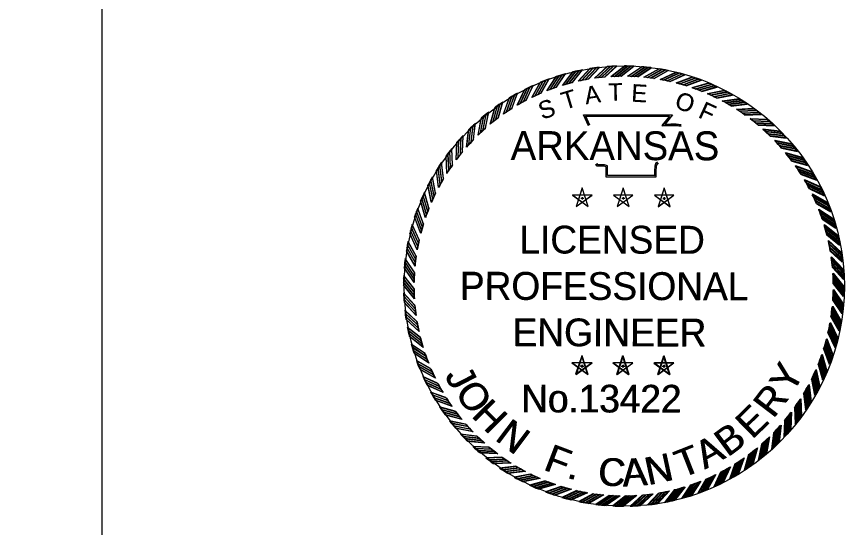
# Model space of a CAD drawing. Extents: x 0 to 38, y -1.3 to 22.5.
# Drawn here: x 33.533 to 38.047, y 15.315 to 18.1 of the extents above; entities that cross this region are included whole.
import ezdxf

# ---------------------------------------------------------------- set-up
doc = ezdxf.new("R2010")
doc.units = 0
for name, color, linetype in [('Default', 7, 'Continuous'), ('G-ANNO-STMP', 7, 'Continuous'), ('G-Border-Paper', 7, 'Continuous'), ('G-No Plot-Stamp-1', 7, 'Continuous'), ('G-No Plot-Stamp-2', 7, 'Continuous')]:
    doc.layers.add(name, color=color, linetype=linetype)

# ---------------------------------------------------------------- blocks, each defined once
blk = doc.blocks.new('STAR')
at = {"layer": 'Default'}
for p, q in [((-0.0001, 0.0615), (-0.0366, -0.0504)), ((0.0362, -0.0503), (0, 0.0617)), ((0.0587, 0.0188), (-0.059, 0.0189)), ((-0.0589, 0.0188), (0.0363, -0.0505)), ((-0.0365, -0.0503), (0.0589, 0.0188)), ((-0.0085, 0), (0.009, 0)), ((0, 0.0063), (0, -0.0085))]:
    blk.add_line(p, q, dxfattribs=at)
blk = doc.blocks.new('RP')
at = {"layer": 'Default'}
for p, q in [((-0.0781, 1.2656), (0.003, 1.33)), ((-0.058, 1.2667), (0.0216, 1.3299)), ((-0.0375, 1.2674), (0.0405, 1.3294)), ((-0.0176, 1.2679), (0.059, 1.3287))]:
    blk.add_line(p, q, dxfattribs=at)
for radius, start, end in [(1.33, 87.4562, 89.8699), (1.268, 90.7933, 93.5307)]:
    blk.add_arc((0, 0), radius, start, end, dxfattribs=at)

msp = doc.modelspace()

# ---------------------------------------------------------------- linework, layer by layer
at = {"layer": 'G-ANNO-STMP'}
for points in [[(36.6512, 17.5042), (36.6231, 17.5649), (37.1083, 17.5652), (37.0678, 17.5142), (37.1007, 17.5147), (37.1283, 17.515), (37.1558, 17.512)], [(36.6521, 17.5045), (36.6243, 17.5653), (37.1095, 17.5639), (37.0688, 17.5131), (37.1017, 17.5135), (37.1293, 17.5137), (37.1568, 17.5106)], [(36.6581, 17.5074), (36.6351, 17.5572), (37.0924, 17.5575), (37.0517, 17.5063), (37.1008, 17.507), (37.1279, 17.5073), (37.1549, 17.5044)], [(36.6591, 17.5077), (36.6363, 17.5576), (37.0935, 17.5563), (37.0526, 17.5053), (37.1018, 17.5058), (37.1289, 17.506), (37.1559, 17.503)], [(37.0319, 17.3008), (37.0236, 17.2941), (37.0208, 17.284), (37.0181, 17.2589), (37.0181, 17.2253), (36.7472, 17.2253), (36.7472, 17.2706), (36.7472, 17.2807), (36.7363, 17.284), (36.6977, 17.284), (36.6909, 17.2945)], [(37.0321, 17.2999), (37.0238, 17.2931), (37.021, 17.2831), (37.0182, 17.258), (37.0181, 17.2244), (36.7472, 17.2253), (36.7474, 17.2706), (36.7474, 17.2807), (36.7365, 17.2841), (36.6979, 17.2842), (36.6911, 17.2947)], [(37.027, 17.3068), (37.0168, 17.2985), (37.0133, 17.2855), (37.0104, 17.2593), (37.0104, 17.233), (36.7549, 17.233), (36.7549, 17.2706), (36.7549, 17.2864), (36.7374, 17.2917), (36.7019, 17.2917), (36.6973, 17.2987)], [(37.0273, 17.3058), (37.0171, 17.2976), (37.0135, 17.2846), (37.0105, 17.2584), (37.0104, 17.2321), (36.7549, 17.233), (36.7551, 17.2706), (36.7551, 17.2863), (36.7376, 17.2918), (36.7021, 17.2919), (36.6976, 17.2989)]]:
    msp.add_lwpolyline(points, dxfattribs=at)
at = {"layer": 'G-Border-Paper'}
msp.add_lwpolyline([(34, 22), (0, 22), (0, 0), (34, 0)], close=True, dxfattribs=at)
at = {"layer": 'G-No Plot-Stamp-1'}
msp.add_circle((36.8467, 16.6309), 1.2, dxfattribs=at)
at = {"layer": 'G-No Plot-Stamp-2'}
msp.add_circle((36.8467, 16.6309), 1.2, dxfattribs=at)

# ---------------------------------------------------------------- block references
at = {"layer": 'G-ANNO-STMP'}
for name, p, xscale, yscale, rotation in [('RP', (36.8439, 16.6311), 0.9020715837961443, 0.9020715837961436, 4.500000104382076), ('RP', (36.8418, 16.6308), 0.902071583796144, 0.9020715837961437, 4.304199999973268), ('RP', (36.8439, 16.6311), 0.902071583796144, 0.9020715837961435, 1.0438208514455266e-07), ('RP', (36.8418, 16.6308), 0.902071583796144, 0.9020715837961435, -0.19580000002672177), ('RP', (36.8439, 16.6311), 0.902071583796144, 0.9020715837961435, -4.499999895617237), ('RP', (36.8418, 16.6308), 0.9020715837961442, 0.9020715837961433, -4.695800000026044), ('RP', (36.8439, 16.6311), 0.9020715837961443, 0.9020715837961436, 18.000000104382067), ('RP', (36.8418, 16.6308), 0.9020715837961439, 0.9020715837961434, 17.804199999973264), ('RP', (36.8439, 16.6311), 0.9020715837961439, 0.9020715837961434, 13.500000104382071), ('RP', (36.8418, 16.6308), 0.902071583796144, 0.9020715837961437, 13.304199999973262), ('RP', (36.8439, 16.6311), 0.9020715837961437, 0.9020715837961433, 9.000000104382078), ('RP', (36.8418, 16.6308), 0.9020715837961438, 0.9020715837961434, 8.804199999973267), ('RP', (36.8439, 16.6311), 0.9020715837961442, 0.9020715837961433, -8.999999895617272), ('RP', (36.8418, 16.6308), 0.9020715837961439, 0.9020715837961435, -9.195800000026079), ('RP', (36.8439, 16.6311), 0.9020715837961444, 0.9020715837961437, -13.499999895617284), ('RP', (36.8418, 16.6308), 0.9020715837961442, 0.9020715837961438, -13.695800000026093), ('RP', (36.8439, 16.6311), 0.9020715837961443, 0.9020715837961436, -17.99999989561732), ('RP', (36.8418, 16.6308), 0.9020715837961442, 0.9020715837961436, -18.19580000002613), ('RP', (36.8439, 16.6311), 0.9020715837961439, 0.9020715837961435, 22.500000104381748), ('RP', (36.8418, 16.6308), 0.902071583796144, 0.9020715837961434, 22.304199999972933), ('RP', (36.8439, 16.6311), 0.9020715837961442, 0.9020715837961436, -22.499999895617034), ('RP', (36.8418, 16.6308), 0.9020715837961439, 0.9020715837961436, -22.695800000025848), ('RP', (36.8439, 16.6311), 0.902071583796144, 0.9020715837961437, 27.000000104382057), ('RP', (36.8418, 16.6308), 0.9020715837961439, 0.9020715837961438, 26.804199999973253), ('RP', (36.8439, 16.6311), 0.9020715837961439, 0.9020715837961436, -26.999999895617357), ('RP', (36.8418, 16.6308), 0.9020715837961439, 0.9020715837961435, -27.19580000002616), ('RP', (36.8439, 16.6311), 0.9020715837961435, 0.9020715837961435, 31.50000010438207), ('RP', (36.8418, 16.6308), 0.9020715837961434, 0.9020715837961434, 31.30419999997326), ('RP', (36.8439, 16.6311), 0.9020715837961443, 0.9020715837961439, -31.499999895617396), ('RP', (36.8418, 16.6308), 0.9020715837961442, 0.9020715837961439, -31.695800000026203), ('RP', (36.8439, 16.6311), 0.9020715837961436, 0.9020715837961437, 36.00000010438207), ('RP', (36.8418, 16.6308), 0.9020715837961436, 0.9020715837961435, 35.80419999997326), ('RP', (36.8439, 16.6311), 0.9020715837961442, 0.902071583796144, -35.999999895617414), ('RP', (36.8418, 16.6308), 0.902071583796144, 0.9020715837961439, -36.195800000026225), ('RP', (36.8439, 16.6311), 0.9020715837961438, 0.9020715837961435, 40.50000010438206), ('RP', (36.8418, 16.6308), 0.9020715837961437, 0.9020715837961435, 40.30419999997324), ('RP', (36.8439, 16.6311), 0.9020715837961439, 0.902071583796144, -40.49999989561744), ('RP', (36.8418, 16.6308), 0.9020715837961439, 0.9020715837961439, -40.69580000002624), ('RP', (36.8439, 16.6311), 0.9020715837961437, 0.902071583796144, 45.00000010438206), ('RP', (36.8418, 16.6308), 0.9020715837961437, 0.9020715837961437, 44.80419999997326), ('RP', (36.8439, 16.6311), 0.9020715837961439, 0.9020715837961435, -44.99999989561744), ('RP', (36.8418, 16.6308), 0.9020715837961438, 0.9020715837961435, -45.19580000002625), ('RP', (36.8439, 16.6311), 0.9020715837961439, 0.902071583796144, 49.500000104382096), ('RP', (36.8418, 16.6308), 0.902071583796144, 0.902071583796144, 49.304199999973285), ('RP', (36.8439, 16.6311), 0.9020715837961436, 0.9020715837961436, -49.499999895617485), ('RP', (36.8418, 16.6308), 0.9020715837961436, 0.9020715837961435, -49.695800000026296), ('RP', (36.8439, 16.6311), 0.9020715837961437, 0.9020715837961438, 54.00000010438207), ('RP', (36.8418, 16.6308), 0.9020715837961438, 0.9020715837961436, 53.804199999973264), ('RP', (36.8439, 16.6311), 0.9020715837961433, 0.9020715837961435, -53.999999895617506), ('RP', (36.8418, 16.6308), 0.9020715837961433, 0.9020715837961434, -54.1958000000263), ('RP', (36.8418, 16.6308), 0.9020715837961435, 0.9020715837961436, 58.304199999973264), ('RP', (36.8439, 16.6311), 0.9020715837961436, 0.9020715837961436, 58.50000010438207), ('RP', (36.8439, 16.6311), 0.9020715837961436, 0.9020715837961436, -58.49999989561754), ('RP', (36.8418, 16.6308), 0.9020715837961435, 0.9020715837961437, -58.69580000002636), ('RP', (36.8418, 16.6308), 0.9020715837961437, 0.9020715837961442, 62.804199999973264), ('RP', (36.8439, 16.6311), 0.9020715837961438, 0.902071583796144, 63.00000010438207), ('RP', (36.8418, 16.6308), 0.9020715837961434, 0.9020715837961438, -63.19580000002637), ('RP', (36.8439, 16.6311), 0.9020715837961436, 0.9020715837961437, -62.99999989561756), ('STAR', (36.617, 17.1105), 0.902071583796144, 0.9020715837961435, -0.19580000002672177), ('STAR', (36.6174, 17.1101), 0.902071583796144, 0.9020715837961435, 1.0438208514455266e-07), ('STAR', (36.8401, 17.1098), 0.902071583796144, 0.9020715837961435, -0.19580000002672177), ('STAR', (36.8405, 17.1101), 0.902071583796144, 0.9020715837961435, 1.0438208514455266e-07), ('STAR', (37.0633, 17.109), 0.902071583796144, 0.9020715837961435, -0.19580000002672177), ('STAR', (37.0637, 17.1101), 0.902071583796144, 0.9020715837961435, 1.0438208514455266e-07), ('RP', (36.8439, 16.6311), 0.9020715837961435, 0.9020715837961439, -67.49999989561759), ('RP', (36.8418, 16.6308), 0.9020715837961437, 0.9020715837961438, 67.30419999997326), ('RP', (36.8439, 16.6311), 0.9020715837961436, 0.9020715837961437, 67.50000010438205), ('RP', (36.8418, 16.6308), 0.9020715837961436, 0.9020715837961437, -67.69580000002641), ('RP', (36.8418, 16.6308), 0.9020715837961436, 0.9020715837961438, -72.19580000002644), ('RP', (36.8439, 16.6311), 0.9020715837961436, 0.9020715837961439, -71.99999989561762), ('RP', (36.8418, 16.6308), 0.9020715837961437, 0.902071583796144, 71.80419999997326), ('RP', (36.8439, 16.6311), 0.9020715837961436, 0.9020715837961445, 72.00000010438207), ('RP', (36.8418, 16.6308), 0.9020715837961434, 0.9020715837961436, -76.69580000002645), ('RP', (36.8439, 16.6311), 0.9020715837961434, 0.9020715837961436, -76.49999989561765), ('RP', (36.8418, 16.6308), 0.9020715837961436, 0.9020715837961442, 76.30419999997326), ('RP', (36.8439, 16.6311), 0.9020715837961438, 0.902071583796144, 76.50000010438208), ('RP', (36.8418, 16.6308), 0.9020715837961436, 0.9020715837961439, -81.19580000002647), ('RP', (36.8439, 16.6311), 0.9020715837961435, 0.9020715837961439, -80.99999989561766), ('RP', (36.8418, 16.6308), 0.9020715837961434, 0.9020715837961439, 80.80419999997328), ('RP', (36.8439, 16.6311), 0.9020715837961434, 0.902071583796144, 81.0000001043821), ('RP', (36.8439, 16.6311), 0.9020715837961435, 0.9020715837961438, -85.49999989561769), ('RP', (36.8418, 16.6308), 0.9020715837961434, 0.9020715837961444, 85.30419999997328), ('RP', (36.8439, 16.6311), 0.9020715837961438, 0.9020715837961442, 85.5000001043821), ('RP', (36.8418, 16.6308), 0.9020715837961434, 0.9020715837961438, -85.69580000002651), ('RP', (36.8418, 16.6308), 0.9020715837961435, 0.902071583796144, 89.80419999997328), ('RP', (36.8439, 16.6311), 0.9020715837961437, 0.9020715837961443, 90.0000001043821), ('RP', (36.8418, 16.6308), 0.9020715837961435, 0.902071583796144, -90.19580000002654), ('RP', (36.8439, 16.6311), 0.9020715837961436, 0.9020715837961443, -89.99999989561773), ('RP', (36.8418, 16.6308), 0.9020715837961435, 0.9020715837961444, 94.30419999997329), ('RP', (36.8439, 16.6311), 0.9020715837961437, 0.9020715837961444, 94.5000001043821), ('RP', (36.8418, 16.6308), 0.9020715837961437, 0.902071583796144, -94.69580000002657), ('RP', (36.8439, 16.6311), 0.9020715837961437, 0.902071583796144, -94.49999989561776), ('RP', (36.8439, 16.6311), 0.9020715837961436, 0.9020715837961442, -98.99999989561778), ('RP', (36.8418, 16.6308), 0.9020715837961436, 0.9020715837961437, 98.8041999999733), ('RP', (36.8439, 16.6311), 0.9020715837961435, 0.9020715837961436, 99.0000001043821), ('RP', (36.8418, 16.6308), 0.9020715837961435, 0.9020715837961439, -99.19580000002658), ('RP', (36.8439, 16.6311), 0.9020715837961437, 0.9020715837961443, -103.49999989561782), ('RP', (36.8418, 16.6308), 0.9020715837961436, 0.9020715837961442, 103.30419999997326), ('RP', (36.8439, 16.6311), 0.9020715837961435, 0.902071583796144, 103.50000010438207), ('RP', (36.8418, 16.6308), 0.9020715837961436, 0.9020715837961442, -103.69580000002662), ('RP', (36.8418, 16.6308), 0.9020715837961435, 0.9020715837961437, -108.19580000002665), ('RP', (36.8439, 16.6311), 0.9020715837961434, 0.902071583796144, -107.99999989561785), ('RP', (36.8418, 16.6308), 0.9020715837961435, 0.9020715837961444, 107.80419999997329), ('RP', (36.8439, 16.6311), 0.9020715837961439, 0.9020715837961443, 108.0000001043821), ('STAR', (36.6139, 16.1956), 0.902071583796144, 0.9020715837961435, -0.19580000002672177), ('STAR', (36.6174, 16.1951), 0.902071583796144, 0.9020715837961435, 1.0438208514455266e-07), ('STAR', (36.837, 16.1948), 0.902071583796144, 0.9020715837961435, -0.19580000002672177), ('STAR', (36.8405, 16.1951), 0.902071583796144, 0.9020715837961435, 1.0438208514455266e-07), ('STAR', (37.0637, 16.1951), 0.902071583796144, 0.9020715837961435, 1.0438208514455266e-07), ('RP', (36.8418, 16.6308), 0.9020715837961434, 0.9020715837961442, -112.69580000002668), ('RP', (36.8439, 16.6311), 0.9020715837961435, 0.9020715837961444, -112.49999989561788), ('RP', (36.8418, 16.6308), 0.9020715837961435, 0.9020715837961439, 112.30419999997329), ('RP', (36.8439, 16.6311), 0.9020715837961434, 0.9020715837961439, 112.5000001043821), ('STAR', (37.0601, 16.1941), 0.902071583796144, 0.9020715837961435, -0.19580000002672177), ('RP', (36.8418, 16.6308), 0.9020715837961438, 0.9020715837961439, 116.80419999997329), ('RP', (36.8418, 16.6308), 0.9020715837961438, 0.9020715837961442, -117.19580000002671), ('RP', (36.8439, 16.6311), 0.902071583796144, 0.9020715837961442, -116.9999998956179), ('RP', (36.8439, 16.6311), 0.9020715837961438, 0.9020715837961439, 117.0000001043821), ('RP', (36.8418, 16.6308), 0.9020715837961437, 0.9020715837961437, 121.30419999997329), ('RP', (36.8439, 16.6311), 0.9020715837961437, 0.9020715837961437, 121.5000001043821), ('RP', (36.8418, 16.6308), 0.9020715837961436, 0.9020715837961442, -121.69580000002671), ('RP', (36.8439, 16.6311), 0.9020715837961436, 0.9020715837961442, -121.4999998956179), ('RP', (36.8418, 16.6308), 0.9020715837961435, 0.9020715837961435, 125.80419999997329), ('RP', (36.8439, 16.6311), 0.9020715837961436, 0.9020715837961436, 126.00000010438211), ('RP', (36.8418, 16.6308), 0.9020715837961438, 0.9020715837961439, -126.19580000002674), ('RP', (36.8439, 16.6311), 0.9020715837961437, 0.9020715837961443, -125.99999989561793), ('RP', (36.8418, 16.6308), 0.9020715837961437, 0.9020715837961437, -130.6958000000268), ('RP', (36.8439, 16.6311), 0.9020715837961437, 0.9020715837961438, -130.49999989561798), ('RP', (36.8418, 16.6308), 0.9020715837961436, 0.9020715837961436, 130.3041999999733), ('RP', (36.8439, 16.6311), 0.9020715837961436, 0.9020715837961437, 130.50000010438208), ('RP', (36.8418, 16.6308), 0.9020715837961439, 0.9020715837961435, 134.80419999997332), ('RP', (36.8439, 16.6311), 0.9020715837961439, 0.9020715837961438, 135.00000010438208), ('RP', (36.8418, 16.6308), 0.9020715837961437, 0.9020715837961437, -135.19580000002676), ('RP', (36.8439, 16.6311), 0.9020715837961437, 0.902071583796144, -134.99999989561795), ('RP', (36.8418, 16.6308), 0.9020715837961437, 0.9020715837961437, 139.30419999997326), ('RP', (36.8418, 16.6308), 0.9020715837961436, 0.9020715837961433, -139.69580000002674), ('RP', (36.8439, 16.6311), 0.9020715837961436, 0.9020715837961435, -139.49999989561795), ('RP', (36.8439, 16.6311), 0.9020715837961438, 0.9020715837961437, 139.50000010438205), ('RP', (36.8418, 16.6308), 0.902071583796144, 0.9020715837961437, 143.8041999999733), ('RP', (36.8439, 16.6311), 0.9020715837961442, 0.9020715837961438, 144.00000010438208), ('RP', (36.8418, 16.6308), 0.9020715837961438, 0.9020715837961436, -144.19580000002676), ('RP', (36.8439, 16.6311), 0.9020715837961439, 0.9020715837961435, -143.99999989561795), ('RP', (36.8418, 16.6308), 0.9020715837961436, 0.9020715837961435, 148.3041999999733), ('RP', (36.8439, 16.6311), 0.9020715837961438, 0.9020715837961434, 148.50000010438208), ('RP', (36.8418, 16.6308), 0.9020715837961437, 0.9020715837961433, -148.69580000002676), ('RP', (36.8439, 16.6311), 0.9020715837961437, 0.9020715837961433, -148.49999989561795), ('RP', (36.8418, 16.6308), 0.9020715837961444, 0.9020715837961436, 152.8041999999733), ('RP', (36.8439, 16.6311), 0.9020715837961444, 0.9020715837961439, 153.00000010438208), ('RP', (36.8418, 16.6308), 0.9020715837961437, 0.9020715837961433, -153.1958000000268), ('RP', (36.8439, 16.6311), 0.9020715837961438, 0.9020715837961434, -152.99999989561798), ('RP', (36.8418, 16.6308), 0.9020715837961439, 0.9020715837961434, 157.3041999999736), ('RP', (36.8439, 16.6311), 0.9020715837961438, 0.9020715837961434, 157.50000010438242), ('RP', (36.8418, 16.6308), 0.902071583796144, 0.9020715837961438, -157.6958000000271), ('RP', (36.8439, 16.6311), 0.9020715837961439, 0.9020715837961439, -157.4999998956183), ('RP', (36.8418, 16.6308), 0.9020715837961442, 0.9020715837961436, 161.8041999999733), ('RP', (36.8439, 16.6311), 0.9020715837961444, 0.9020715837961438, 162.00000010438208), ('RP', (36.8418, 16.6308), 0.9020715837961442, 0.9020715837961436, 166.3041999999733), ('RP', (36.8439, 16.6311), 0.9020715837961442, 0.9020715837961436, 166.50000010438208), ('RP', (36.8418, 16.6308), 0.902071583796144, 0.9020715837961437, -166.69580000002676), ('RP', (36.8439, 16.6311), 0.9020715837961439, 0.9020715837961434, -166.49999989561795), ('RP', (36.8418, 16.6308), 0.9020715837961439, 0.9020715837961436, -162.19580000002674), ('RP', (36.8439, 16.6311), 0.9020715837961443, 0.9020715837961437, -161.99999989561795), ('RP', (36.8418, 16.6308), 0.9020715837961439, 0.9020715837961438, 170.8041999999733), ('RP', (36.8439, 16.6311), 0.9020715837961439, 0.9020715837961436, 171.00000010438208), ('RP', (36.8418, 16.6308), 0.902071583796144, 0.9020715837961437, 175.3041999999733), ('RP', (36.8439, 16.6311), 0.9020715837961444, 0.9020715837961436, 175.50000010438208), ('RP', (36.8418, 16.6308), 0.902071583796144, 0.9020715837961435, 179.8041999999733), ('RP', (36.8439, 16.6311), 0.9020715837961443, 0.9020715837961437, -179.99999989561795), ('RP', (36.8418, 16.6308), 0.9020715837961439, 0.9020715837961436, -175.69580000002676), ('RP', (36.8439, 16.6311), 0.9020715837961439, 0.9020715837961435, -175.49999989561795), ('RP', (36.8418, 16.6308), 0.9020715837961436, 0.9020715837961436, -171.19580000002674), ('RP', (36.8439, 16.6311), 0.9020715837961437, 0.9020715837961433, -170.99999989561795)]:
    msp.add_blockref(name, p, dxfattribs=dict(at, xscale=xscale, yscale=yscale, rotation=rotation))

# ---------------------------------------------------------------- texts
for s, height, rotation, p in [('T', 0.0957, 16.9015, (36.5202, 17.5906)), ('T', 0.0957, 16.7057, (36.5214, 17.5914)), ('A', 0.0957, 8.6788, (36.6364, 17.621)), ('A', 0.0957, 8.483, (36.6377, 17.6213)), ('T', 0.0957, 1.4789, (36.76, 17.64)), ('T', 0.0957, 1.2831, (36.7614, 17.64)), ('E', 0.0957, 356.672, (36.8824, 17.6371)), ('E', 0.0957, 356.4762, (36.8839, 17.6366)), ('O', 0.0957, 341.2218, (37.1148, 17.6043)), ('O', 0.0957, 341.026, (37.1161, 17.603)), ('S', 0.0957, 19.7726, (36.3985, 17.536)), ('S', 0.0957, 19.5768, (36.3995, 17.5372)), ('F', 0.0957, 335.3628, (37.2438, 17.5538)), ('F', 0.0957, 335.167, (37.2449, 17.5521)), ('ARKANSAS', 0.15621, 0, (36.2265, 17.3183)), ('ARKANSAS', 0.15621, 359.8042, (36.2268, 17.3201)), ('LICENSED', 0.15122, 359.8042, (36.2736, 16.81)), ('LICENSED', 0.15122, 0, (36.275, 16.8084)), ('PROFESSIONAL', 0.151223, 359.8042, (35.9486, 16.5582)), ('PROFESSIONAL', 0.151223, 0, (35.9509, 16.5555)), ('ENGINEER', 0.15122, 359.8042, (36.2358, 16.3043)), ('ENGINEER', 0.15122, 0, (36.239, 16.3026)), ('Y', 0.1512, 62.5392, (37.7637, 16.0373)), ('Y', 0.1512, 62.735, (37.7678, 16.0408)), ('J', 0.1512, 297.2813, (35.8643, 16.1447)), ('J', 0.1512, 297.4771, (35.868, 16.1417)), ('O', 0.1512, 304.1899, (35.9179, 16.052)), ('O', 0.1512, 304.3857, (35.9219, 16.0492)), ('No.13422', 0.15063, 359.8042, (36.2823, 15.9437)), ('No.13422', 0.15063, 0, (36.2867, 15.9421)), ('R', 0.1512, 52.7437, (37.6581, 15.9041)), ('R', 0.1512, 52.9395, (37.6627, 15.9072)), ('H', 0.1512, 314.7447, (36.0071, 15.9217)), ('H', 0.1512, 314.9405, (36.0116, 15.9192)), ('E', 0.1512, 44.306, (37.5429, 15.7916)), ('E', 0.1512, 44.5018, (37.5478, 15.7943)), ('N', 0.1512, 322.9417, (36.1348, 15.7953)), ('N', 0.1512, 323.1375, (36.1397, 15.7932)), ('B', 0.1512, 36.505, (37.4095, 15.6953)), ('B', 0.1512, 36.7008, (37.4147, 15.6976)), ('A', 0.1512, 28.8562, (37.2839, 15.6293)), ('A', 0.1512, 29.052, (37.2893, 15.6312)), ('F', 0.1512, 339.0288, (36.3988, 15.6315)), ('F', 0.1512, 339.2246, (36.4042, 15.6303)), ('T', 0.1512, 21.4329, (37.1582, 15.582)), ('T', 0.1512, 21.6287, (37.1638, 15.5835)), ('N', 0.1512, 12.0703, (36.9757, 15.5443)), ('N', 0.1512, 12.2661, (36.9815, 15.5451)), ('C', 0.1512, 356.1028, (36.6988, 15.5466)), ('C', 0.1512, 356.2986, (36.7045, 15.5465)), ('A', 0.1512, 3.9092, (36.8375, 15.5366)), ('A', 0.1512, 4.105, (36.8433, 15.5369)), ('.', 0.1512, 344.7037, (36.5278, 15.5868)), ('.', 0.1512, 344.8995, (36.5334, 15.586))]:
    msp.add_text(s, height=height, rotation=rotation, dxfattribs=at).set_placement(p)

doc.saveas('drawing.dxf')
